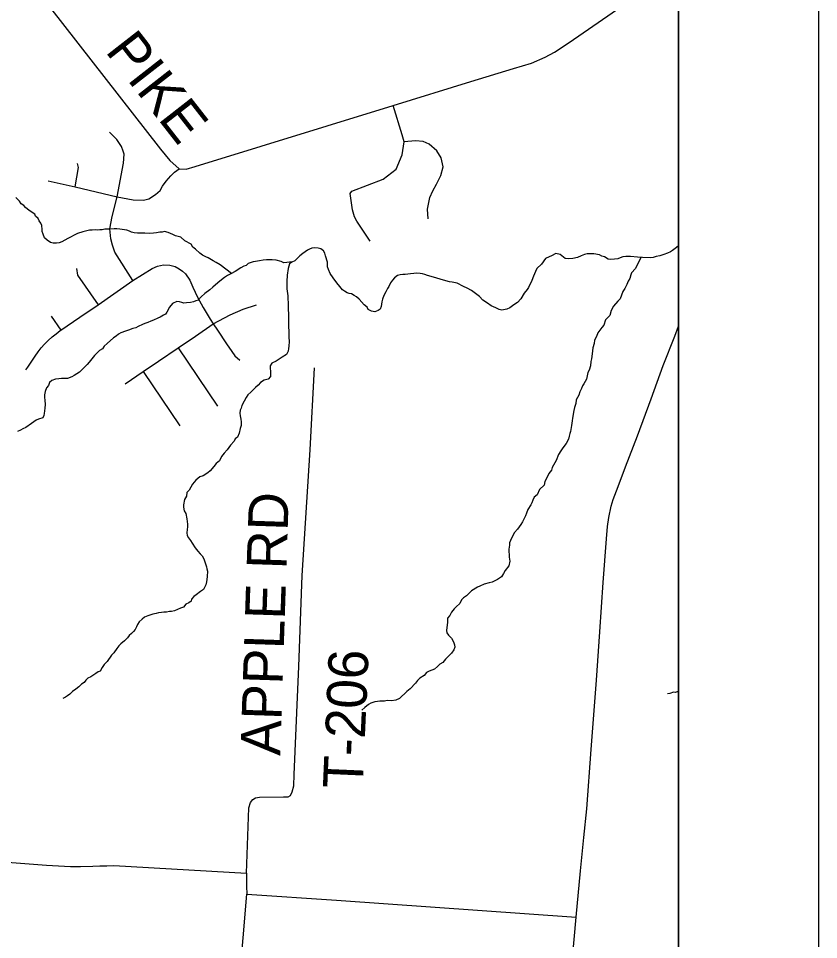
# Model space of a CAD drawing. Extents: x 0 to 34, y 0 to 22.
# Drawn here: x 8.429 to 9, y 14.941 to 15.599 of the extents above; entities that cross this region are included whole.
import ezdxf

# ---------------------------------------------------------------- set-up
doc = ezdxf.new("R2010")
doc.units = 0
for name, color, linetype in [('GM_X_Corporation', 7, 'Continuous'), ('GM_X_County_Road', 7, 'Continuous'), ('GM_X_County_Road_Text', 7, 'Continuous'), ('GM_X_Minor_River', 7, 'Continuous'), ('GM_X_State_Route', 7, 'Continuous'), ('GM_X_Township_Road', 7, 'Continuous'), ('GM_X_Township_Road_Text', 7, 'Continuous'), ('SH_Cut_Line', 7, 'Continuous'), ('SH_Data', 7, 'Continuous')]:
    doc.layers.add(name, color=color, linetype=linetype)

msp = doc.modelspace()

# ---------------------------------------------------------------- linework, layer by layer
at = {"layer": 'GM_X_Corporation'}
msp.add_lwpolyline([(8.9, 14.1), (8.9, 17.02104)], dxfattribs=at)
at = {"layer": 'GM_X_County_Road'}
msp.add_lwpolyline([(8.3737, 15.57239), (8.442, 15.61944), (8.5305, 15.50572), (8.53704, 15.49756), (8.54379, 15.4917), (8.54871, 15.49138), (8.5552, 15.4933), (8.69651, 15.53687), (8.75195, 15.55397), (8.78224, 15.56322), (8.79512, 15.56721), (8.80491, 15.57138), (8.81162, 15.57501), (8.82214, 15.5819), (8.89723, 15.63395), (8.9, 15.63583)], dxfattribs=at)
at = {"layer": 'GM_X_Minor_River'}
for points in [[(8.58106, 15.417), (8.57312, 15.42317), (8.5703, 15.42474), (8.56804, 15.42592), (8.56446, 15.42807), (8.56276, 15.42886), (8.5605, 15.43004), (8.55863, 15.43159), (8.55544, 15.43431), (8.55357, 15.43586), (8.55227, 15.43798), (8.54775, 15.44034), (8.54494, 15.44286), (8.54304, 15.44327), (8.54115, 15.44387), (8.53927, 15.44486), (8.53606, 15.44624), (8.53341, 15.44686), (8.53169, 15.44651), (8.52998, 15.44635), (8.52769, 15.44601), (8.5256, 15.44567), (8.52274, 15.44553), (8.51933, 15.44578), (8.51648, 15.44583), (8.514, 15.44568), (8.51172, 15.44591), (8.50983, 15.44651), (8.50832, 15.44711), (8.50643, 15.4479), (8.50321, 15.44834), (8.5015, 15.44856), (8.49942, 15.44879), (8.49733, 15.44882), (8.49428, 15.44868), (8.49238, 15.44853), (8.49067, 15.44856), (8.48876, 15.44821), (8.48724, 15.44805), (8.48533, 15.44789), (8.48382, 15.44811), (8.48172, 15.44795), (8.47982, 15.4478), (8.47696, 15.44728), (8.47505, 15.44674), (8.47123, 15.44548), (8.46931, 15.44456), (8.46586, 15.44272), (8.46433, 15.44199), (8.46221, 15.44069), (8.4601, 15.43959), (8.45819, 15.43886), (8.45629, 15.43871), (8.454, 15.43856), (8.45211, 15.43897), (8.44967, 15.44072), (8.44761, 15.44247), (8.4467, 15.44496), (8.44616, 15.44687), (8.44599, 15.44839), (8.44585, 15.45124), (8.44512, 15.45278), (8.44382, 15.45451), (8.44327, 15.45623), (8.4414, 15.45778), (8.44086, 15.45931), (8.43672, 15.46205), (8.43428, 15.46399), (8.43298, 15.46553), (8.43109, 15.46671), (8.42999, 15.46863), (8.42718, 15.47115)], [(8.84996, 15.42725), (8.84732, 15.42882), (8.84543, 15.42942), (8.84374, 15.43021), (8.83957, 15.43104), (8.83786, 15.43107), (8.835, 15.43093), (8.83291, 15.43059), (8.83061, 15.42968), (8.82812, 15.42839), (8.82468, 15.42769), (8.82183, 15.42736), (8.81917, 15.4276), (8.81561, 15.43051), (8.81258, 15.43133), (8.80951, 15.42967), (8.80779, 15.42894), (8.80511, 15.42766), (8.80238, 15.42371), (8.79909, 15.42054), (8.79811, 15.41847), (8.79653, 15.41507), (8.79553, 15.41205), (8.79316, 15.40696), (8.792, 15.40546), (8.79005, 15.40283), (8.78751, 15.39888), (8.78519, 15.39626), (8.78269, 15.3946), (8.77961, 15.39256), (8.7775, 15.39146), (8.77407, 15.39076), (8.77218, 15.39117), (8.76973, 15.39254), (8.76633, 15.39393), (8.7637, 15.39588), (8.76051, 15.39803), (8.75808, 15.40054), (8.75526, 15.40268), (8.75226, 15.40482), (8.74924, 15.4064), (8.7466, 15.40758), (8.74208, 15.40994), (8.73848, 15.41077), (8.73677, 15.41099), (8.73242, 15.4122), (8.72524, 15.41442), (8.72088, 15.41564), (8.71918, 15.41624), (8.71748, 15.41665), (8.71577, 15.41687), (8.71331, 15.4171), (8.71121, 15.41695), (8.70893, 15.41661), (8.70702, 15.41645), (8.70512, 15.41629), (8.7034, 15.41613), (8.7015, 15.41598), (8.69959, 15.41544), (8.69747, 15.41396), (8.69592, 15.41208), (8.69456, 15.41021), (8.69338, 15.40776), (8.6924, 15.40625), (8.69122, 15.4038), (8.68985, 15.40117), (8.68886, 15.39871), (8.68844, 15.39663), (8.68823, 15.39511), (8.68801, 15.39341), (8.68721, 15.39152), (8.68568, 15.3906), (8.68338, 15.38968), (8.68092, 15.39011), (8.67866, 15.39129), (8.67792, 15.39282), (8.67586, 15.39457), (8.67232, 15.39862), (8.67044, 15.40018), (8.66875, 15.40116), (8.66687, 15.40233), (8.66516, 15.40274), (8.66365, 15.40315), (8.66177, 15.40432), (8.66026, 15.4053), (8.6584, 15.40761), (8.65636, 15.41031), (8.65376, 15.41396), (8.65152, 15.41685), (8.65024, 15.41973), (8.6497, 15.42164), (8.64957, 15.42506), (8.64832, 15.42964), (8.64778, 15.43155), (8.64685, 15.43309), (8.64478, 15.43446), (8.64289, 15.43506), (8.64062, 15.43529), (8.63852, 15.43495), (8.6368, 15.43441), (8.63527, 15.43367)], [(8.9, 15.4368), (8.89857, 15.43552), (8.89588, 15.43348), (8.89434, 15.43236), (8.89223, 15.43145), (8.88955, 15.43055), (8.88669, 15.42965), (8.88402, 15.42912), (8.88191, 15.4284), (8.88001, 15.42824), (8.8745, 15.42834), (8.8707, 15.4286), (8.86577, 15.42906), (8.86254, 15.42912), (8.86044, 15.42878), (8.85834, 15.42824), (8.85681, 15.42751), (8.85433, 15.42717), (8.85148, 15.42703), (8.84996, 15.42725)], [(8.63527, 15.43367), (8.63199, 15.43126), (8.62988, 15.42959), (8.62814, 15.42791), (8.62639, 15.42604), (8.6241, 15.42494), (8.62256, 15.42382), (8.62196, 15.42212), (8.62155, 15.42042), (8.6209, 15.41587), (8.62064, 15.41131), (8.62058, 15.40808), (8.62074, 15.40599), (8.62106, 15.40275), (8.62122, 15.40104), (8.62137, 15.39875), (8.62152, 15.39628), (8.62146, 15.39229), (8.62162, 15.39077), (8.62178, 15.38867), (8.62174, 15.38658), (8.62186, 15.38259), (8.6218, 15.37879), (8.62213, 15.37574), (8.62206, 15.37156), (8.6222, 15.36852), (8.62214, 15.3651), (8.62192, 15.36339), (8.62151, 15.3615), (8.62033, 15.35905), (8.61726, 15.3572), (8.61514, 15.35572), (8.61303, 15.35443), (8.60996, 15.35296), (8.60879, 15.35108), (8.60876, 15.34937), (8.60891, 15.34709), (8.60907, 15.34537), (8.60904, 15.34347), (8.6073, 15.3416), (8.60444, 15.34089), (8.60194, 15.33923), (8.60019, 15.33717), (8.59826, 15.33549), (8.59498, 15.33213), (8.59286, 15.33045), (8.59168, 15.32838), (8.59012, 15.32575), (8.58855, 15.32274), (8.58794, 15.32085), (8.58735, 15.31934), (8.58712, 15.31725), (8.58728, 15.31535), (8.58781, 15.31306), (8.58797, 15.31115), (8.58793, 15.30849), (8.58732, 15.30641), (8.5865, 15.30301), (8.58551, 15.30017), (8.58377, 15.29887), (8.58299, 15.29736), (8.58047, 15.29437), (8.57794, 15.29118), (8.57581, 15.28875), (8.57406, 15.28631), (8.57249, 15.28329), (8.57017, 15.28125), (8.56843, 15.27918), (8.5659, 15.27619), (8.56436, 15.27469), (8.5609, 15.27248), (8.55861, 15.27175), (8.55572, 15.26952), (8.55339, 15.26652), (8.55103, 15.26219), (8.5493, 15.2607), (8.54906, 15.25805), (8.5475, 15.2556), (8.54687, 15.25181), (8.54684, 15.2501), (8.54736, 15.24743), (8.54847, 15.24551), (8.54917, 15.24189), (8.54952, 15.23998), (8.54967, 15.23789), (8.54965, 15.23618), (8.54942, 15.23409), (8.54919, 15.23182), (8.54954, 15.22991), (8.55046, 15.22818), (8.55195, 15.22645), (8.55306, 15.22434), (8.55529, 15.22107), (8.55715, 15.21875), (8.55883, 15.21682), (8.56032, 15.21528), (8.56143, 15.21317), (8.5627, 15.20972), (8.56323, 15.20762), (8.56359, 15.2061), (8.56394, 15.20438)], [(8.87311, 15.42843), (8.86943, 15.42064), (8.86652, 15.41746), (8.86612, 15.41594), (8.86532, 15.41349), (8.86414, 15.41142), (8.86315, 15.40915), (8.86177, 15.40632), (8.86041, 15.40407), (8.85842, 15.39897), (8.85668, 15.3971), (8.85377, 15.39354), (8.852, 15.39053), (8.85099, 15.38694), (8.84809, 15.38395), (8.84669, 15.37998), (8.84534, 15.37829), (8.84242, 15.37454), (8.84162, 15.37209), (8.84025, 15.36945), (8.83982, 15.36699), (8.83901, 15.36396), (8.83856, 15.35959), (8.83793, 15.35599), (8.83752, 15.3541), (8.83728, 15.35106), (8.83627, 15.34804), (8.83549, 15.34634), (8.83446, 15.34161), (8.8325, 15.33822), (8.83152, 15.33672), (8.83092, 15.33483), (8.82974, 15.33257), (8.82894, 15.33011), (8.82717, 15.32672), (8.82675, 15.32426), (8.82575, 15.32124), (8.82534, 15.31915), (8.82448, 15.31365), (8.82426, 15.31176), (8.82364, 15.30854), (8.82299, 15.30418), (8.82259, 15.30266), (8.82198, 15.30077), (8.82157, 15.29869), (8.81981, 15.29549), (8.81747, 15.29249), (8.81611, 15.29042), (8.81454, 15.28779), (8.81276, 15.28345), (8.80982, 15.27837), (8.80941, 15.27647), (8.80766, 15.27422), (8.80648, 15.27158), (8.80472, 15.26857), (8.80429, 15.26592), (8.80101, 15.26275), (8.79923, 15.25898), (8.79711, 15.2573), (8.79613, 15.25504), (8.79553, 15.25334), (8.79474, 15.25183), (8.79259, 15.24845), (8.7916, 15.24581), (8.791, 15.24392), (8.78884, 15.23977), (8.78747, 15.23771), (8.78514, 15.23452), (8.783, 15.23208), (8.78084, 15.22794), (8.77946, 15.22473), (8.77943, 15.22302), (8.779, 15.22018), (8.77929, 15.21447), (8.77962, 15.21161), (8.77899, 15.2082), (8.77647, 15.20483), (8.77529, 15.20276), (8.77373, 15.20031), (8.77085, 15.19846), (8.76912, 15.19754), (8.76701, 15.19663), (8.76491, 15.19609), (8.76148, 15.19521), (8.75822, 15.19374), (8.75669, 15.19301), (8.75246, 15.19042), (8.74879, 15.18687), (8.74668, 15.18539), (8.74513, 15.18409), (8.74413, 15.18125), (8.74144, 15.17902), (8.74008, 15.17752), (8.73814, 15.17528), (8.73696, 15.17283), (8.73521, 15.17077), (8.73516, 15.16773), (8.73473, 15.16431), (8.7345, 15.16204), (8.73485, 15.16051), (8.73596, 15.15878)], [(8.62466, 15.42521), (8.61858, 15.42465), (8.61669, 15.42564), (8.61291, 15.42646), (8.61006, 15.4267), (8.60607, 15.42677), (8.60378, 15.42643), (8.60111, 15.4261), (8.59825, 15.42558), (8.59654, 15.42523), (8.5931, 15.42415), (8.59155, 15.42265), (8.58983, 15.42211), (8.58791, 15.42101), (8.58369, 15.41842), (8.58062, 15.41676), (8.57831, 15.41547), (8.5762, 15.41399), (8.57408, 15.41232), (8.57138, 15.41027), (8.56772, 15.40711), (8.5656, 15.40524), (8.56213, 15.40264), (8.55943, 15.40041), (8.5573, 15.39798), (8.55577, 15.39743), (8.55405, 15.3967), (8.55195, 15.39636), (8.5491, 15.39603), (8.54719, 15.39587), (8.54568, 15.39628), (8.54397, 15.39669), (8.54208, 15.39691), (8.53901, 15.39545), (8.53688, 15.39282), (8.53511, 15.38943), (8.53413, 15.38793), (8.5326, 15.3872), (8.53029, 15.38572), (8.52857, 15.38518), (8.52551, 15.38371), (8.52359, 15.38298), (8.52148, 15.38188), (8.51938, 15.38116), (8.51766, 15.38043), (8.5146, 15.37915), (8.51287, 15.37823), (8.51077, 15.3777), (8.50771, 15.37661), (8.50542, 15.37589), (8.50216, 15.37462), (8.50044, 15.3737), (8.49889, 15.3722), (8.49697, 15.3711), (8.49234, 15.367), (8.49041, 15.36513), (8.48905, 15.36325), (8.48694, 15.36196), (8.48345, 15.35841), (8.47957, 15.35373), (8.47822, 15.35204), (8.47628, 15.35017), (8.47454, 15.3483), (8.47261, 15.34663), (8.46877, 15.34403), (8.46723, 15.3433), (8.46417, 15.34202), (8.46227, 15.34206), (8.4598, 15.34191), (8.45789, 15.34175), (8.45561, 15.3416), (8.45293, 15.34051), (8.45119, 15.33902), (8.45059, 15.33694), (8.44923, 15.33525), (8.44823, 15.33261), (8.44782, 15.33034), (8.44779, 15.32844), (8.44794, 15.32653), (8.44808, 15.32349), (8.44804, 15.32083), (8.44759, 15.31704), (8.44719, 15.31552), (8.44659, 15.31401), (8.44334, 15.31293), (8.44181, 15.3122), (8.43835, 15.30998), (8.4345, 15.307), (8.4322, 15.30609), (8.43048, 15.30517), (8.42856, 15.30407)], [(8.56394, 15.20438), (8.56369, 15.20058), (8.56346, 15.19849), (8.56324, 15.19679), (8.56283, 15.1947), (8.56106, 15.19131), (8.55914, 15.19002), (8.55586, 15.1876), (8.55432, 15.1863), (8.55258, 15.18443), (8.55236, 15.18291), (8.55063, 15.1818), (8.54853, 15.18089), (8.54697, 15.17864), (8.54468, 15.17811), (8.54046, 15.17609), (8.53837, 15.17575), (8.53684, 15.17558), (8.53475, 15.17524), (8.53284, 15.17508), (8.53113, 15.17492), (8.52903, 15.17458), (8.52732, 15.17423), (8.52503, 15.1737), (8.5214, 15.17263), (8.5191, 15.17152), (8.51737, 15.17022), (8.51524, 15.16836), (8.51407, 15.16629), (8.51328, 15.16478), (8.51249, 15.1629), (8.51132, 15.1614), (8.50978, 15.1599), (8.50824, 15.1586), (8.50688, 15.15691), (8.50475, 15.15467), (8.50224, 15.15262), (8.5007, 15.15113), (8.49934, 15.14925), (8.49719, 15.14625), (8.49564, 15.14438), (8.49234, 15.14006), (8.4904, 15.13782), (8.48884, 15.13575), (8.48747, 15.13312), (8.48594, 15.13257), (8.4844, 15.13146), (8.48286, 15.13035), (8.48075, 15.12905), (8.47864, 15.12814), (8.4771, 15.12665), (8.47612, 15.12495), (8.4742, 15.12385), (8.47227, 15.12198), (8.46996, 15.12031), (8.46764, 15.11845), (8.46571, 15.11658), (8.46417, 15.11547), (8.46264, 15.11455), (8.46091, 15.11344)], [(8.73596, 15.15878), (8.73821, 15.15665), (8.73949, 15.15396), (8.74022, 15.15186), (8.74038, 15.15015), (8.73978, 15.14826), (8.73822, 15.14581), (8.7361, 15.14395), (8.73378, 15.14171), (8.73183, 15.13927), (8.72972, 15.13798), (8.72817, 15.1363), (8.72586, 15.13444), (8.72414, 15.13371), (8.72222, 15.13298), (8.72031, 15.13206), (8.71856, 15.13), (8.71549, 15.12816), (8.71394, 15.12647), (8.71239, 15.12441), (8.70871, 15.12048), (8.7062, 15.11843), (8.70099, 15.11358), (8.69831, 15.1123), (8.69526, 15.11197), (8.69222, 15.11203), (8.69031, 15.11168), (8.6886, 15.11152), (8.68708, 15.11155), (8.68537, 15.11139), (8.68346, 15.11104), (8.68059, 15.11014), (8.67887, 15.10922), (8.67617, 15.10718), (8.67424, 15.10512)], [(8.9, 15.11847), (8.89914, 15.11827), (8.89761, 15.11792), (8.89647, 15.11794), (8.8938, 15.11704), (8.89227, 15.11687)]]:
    msp.add_lwpolyline(points, dxfattribs=at)
at = {"layer": 'GM_X_State_Route'}
for points in [[(8.85198, 15.25089), (8.85351, 15.25555), (8.85705, 15.26496), (8.86219, 15.27896), (8.87075, 15.30107), (8.88059, 15.32744), (8.88919, 15.35126), (8.8975, 15.37231), (8.9, 15.37926)], [(8.81734, 14.8536), (8.81784, 14.85755), (8.82064, 14.88595), (8.82293, 14.91216), (8.82717, 14.95733), (8.83017, 14.99041), (8.83248, 15.01422), (8.83471, 15.03475), (8.83782, 15.07704), (8.84166, 15.12668), (8.84404, 15.16121), (8.84636, 15.19646), (8.84879, 15.22757), (8.8494, 15.23637), (8.85025, 15.24269), (8.85198, 15.25089)]]:
    msp.add_lwpolyline(points, dxfattribs=at)
at = {"layer": 'GM_X_Township_Road'}
for p, q in [((8.70284, 15.51605), (8.69651, 15.53687)), ((8.48594, 15.39469), (8.51079, 15.41192)), ((8.47305, 15.38571), (8.48594, 15.39469)), ((8.45238, 15.38657), (8.45935, 15.37642)), ((8.54314, 15.36388), (8.57127, 15.32221)), ((8.50532, 15.33828), (8.51807, 15.34691)), ((8.51807, 15.34691), (8.54417, 15.30821)), ((8.62911, 15.13629), (8.63149, 15.20139))]:
    msp.add_line(p, q, dxfattribs=at)
for points in [[(8.49966, 15.47179), (8.50415, 15.49562), (8.50454, 15.50206), (8.50396, 15.50421), (8.50259, 15.50753), (8.49927, 15.51261), (8.49419, 15.51788)], [(8.68007, 15.44008), (8.6705, 15.45423), (8.66884, 15.45736), (8.66759, 15.46235), (8.66571, 15.47401), (8.66696, 15.47567), (8.68944, 15.48421), (8.6986, 15.49149), (8.70297, 15.50169), (8.70443, 15.51084), (8.70284, 15.51605)], [(8.72149, 15.4559), (8.72087, 15.46277), (8.72274, 15.4713), (8.72482, 15.47609), (8.72732, 15.48067), (8.73044, 15.48691), (8.73211, 15.49315), (8.73065, 15.49961), (8.72774, 15.5046), (8.72212, 15.50918), (8.71795, 15.51126), (8.71234, 15.51168), (8.70443, 15.51084)], [(8.46959, 15.47882), (8.47192, 15.49266), (8.47134, 15.49542)], [(8.45025, 15.48312), (8.46959, 15.47882), (8.49966, 15.47179), (8.51099, 15.46945), (8.51841, 15.46926), (8.52212, 15.47023), (8.52681, 15.47336), (8.53032, 15.47628), (8.53188, 15.47921), (8.53442, 15.48293), (8.53774, 15.48664), (8.54048, 15.48937), (8.54379, 15.4917)], [(8.51079, 15.41192), (8.49793, 15.43223), (8.49625, 15.43716), (8.49505, 15.44172), (8.49445, 15.44894), (8.49601, 15.45771), (8.49966, 15.47179)], [(8.51079, 15.41192), (8.5245, 15.42045), (8.52834, 15.42225), (8.53267, 15.42309), (8.53724, 15.42297), (8.54096, 15.42189), (8.54385, 15.42033), (8.54625, 15.41865), (8.54829, 15.4166), (8.5513, 15.41216), (8.55358, 15.40711), (8.55695, 15.40002), (8.56103, 15.39269), (8.56584, 15.38427), (8.56812, 15.38103)], [(8.47055, 15.42041), (8.47137, 15.41588), (8.48594, 15.39469)], [(8.56812, 15.38103), (8.58012, 15.38737), (8.58955, 15.39151), (8.59905, 15.39458)], [(8.45935, 15.37642), (8.46397, 15.37959), (8.47305, 15.38571)], [(8.43449, 15.34819), (8.43582, 15.35012), (8.44102, 15.35794), (8.44313, 15.36094), (8.44541, 15.36383), (8.44784, 15.36658), (8.45042, 15.3692), (8.45314, 15.37167), (8.45599, 15.37399), (8.45896, 15.37615), (8.45935, 15.37642)], [(8.54314, 15.36388), (8.55548, 15.37216), (8.56812, 15.38103)], [(8.56812, 15.38103), (8.57113, 15.37646), (8.5775, 15.36684), (8.58135, 15.36132), (8.58361, 15.35818), (8.58712, 15.35507)], [(8.51807, 15.34691), (8.52897, 15.35429), (8.54314, 15.36388)], [(8.63149, 15.20139), (8.63732, 15.29107), (8.64025, 15.34956)], [(8.59184, 14.98886), (8.59353, 15.03537), (8.59477, 15.03932), (8.59634, 15.04136), (8.59827, 15.04264), (8.60112, 15.04314), (8.61817, 15.04327), (8.62158, 15.04337), (8.62312, 15.04428), (8.62452, 15.04689), (8.62558, 15.05123), (8.62597, 15.05919), (8.62852, 15.12001), (8.62911, 15.13629)], [(8.02914, 15.00472), (8.11659, 14.99521), (8.12973, 14.99367), (8.13734, 14.99285), (8.15129, 14.99176), (8.17096, 14.99221), (8.1909, 14.99357), (8.22163, 14.99566), (8.25757, 14.99705), (8.2974, 14.99927), (8.31287, 15.0002), (8.32176, 15.00094), (8.32954, 15.00149), (8.33547, 15.00168), (8.34668, 15.00233), (8.44913, 14.99464), (8.46626, 14.99353), (8.4733, 14.99353), (8.48229, 14.9938), (8.48711, 14.99408), (8.49229, 14.99408), (8.49729, 14.99436), (8.59184, 14.98886)], [(8.59184, 14.98886), (8.59192, 14.97963), (8.59218, 14.97389)], [(8.58688, 14.91138), (8.59218, 14.97389)], [(8.59218, 14.97389), (8.65617, 14.96945), (8.82717, 14.95733)]]:
    msp.add_lwpolyline(points, dxfattribs=at)
at = {"layer": 'SH_Cut_Line'}
msp.add_lwpolyline([(8.9, 14.1), (8.9, 20.9)], dxfattribs=at)
at = {"layer": 'SH_Data'}
for p, q in [((9, 21), (9, 14)), ((8.9, 20.9), (8.9, 14.1))]:
    msp.add_line(p, q, dxfattribs=at)

# ---------------------------------------------------------------- texts
at = {"layer": 'GM_X_County_Road_Text'}
msp.add_text('PIKE', height=0.028409, rotation=307.98314, dxfattribs=at).set_placement((8.49051, 15.57564))
at = {"layer": 'GM_X_Township_Road_Text'}
for s, rotation, p in [('APPLE RD', 88.10497, (8.61589, 15.07255)), ('T-206', 87.47401, (8.67469, 15.04873))]:
    msp.add_text(s, height=0.028409, rotation=rotation, dxfattribs=at).set_placement(p)

doc.saveas('drawing.dxf')
